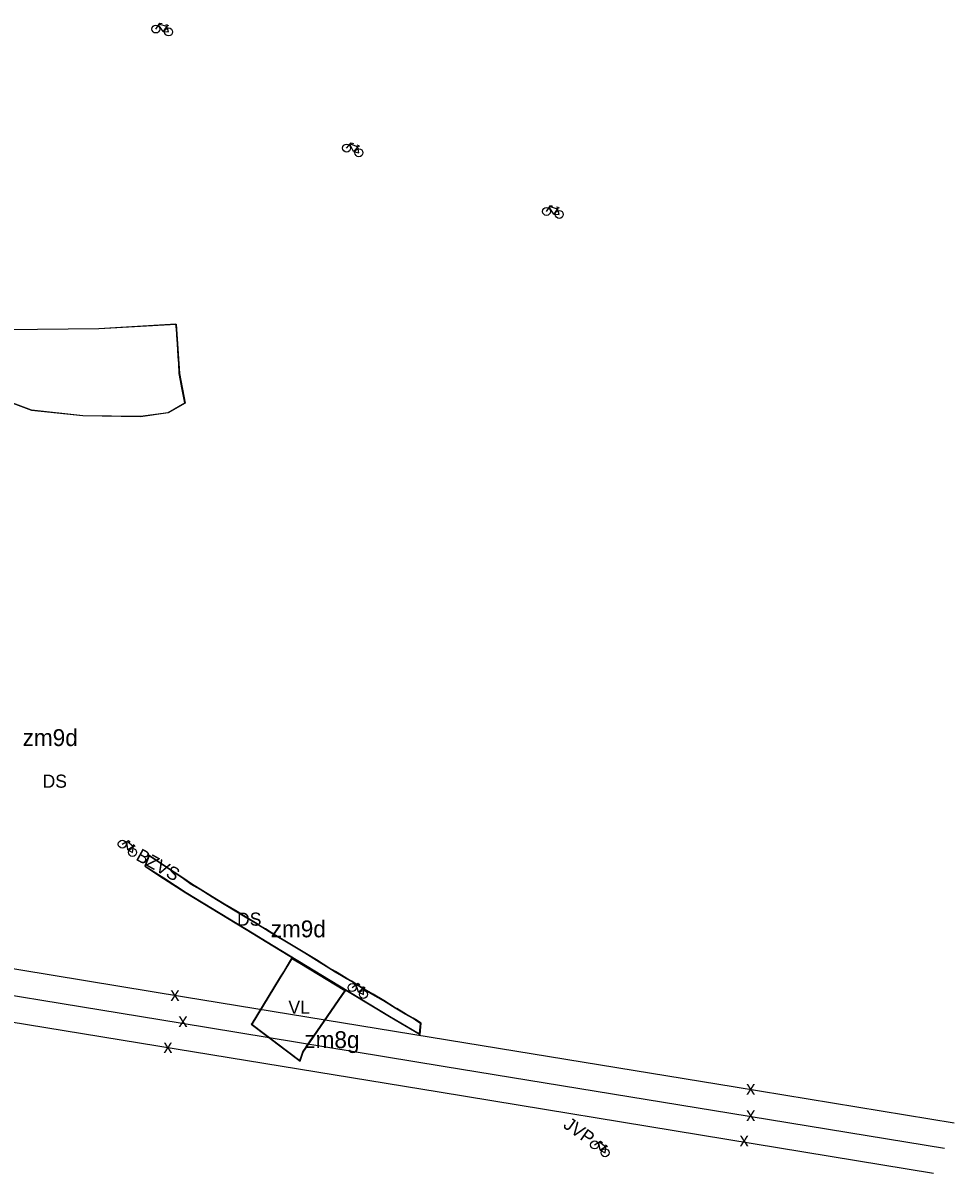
# Model space of a CAD drawing. Extents: x -555070 to -553076, y -1186731 to -1182766.
# Drawn here: x -554069 to -553076, y -1185758 to -1184531 of the extents above; entities that cross this region are included whole.
import ezdxf

# ---------------------------------------------------------------- set-up
doc = ezdxf.new("R2010")
doc.units = 0
for name, color, linetype in [('CYKLISTI_stav', 7, 'Continuous'), ('HRANICE_ZMENY_DO_KOO', 7, 'Continuous'), ('Level 10', 7, 'Continuous'), ('Level 13', 7, 'Continuous'), ('Level 29', 7, 'Continuous'), ('Level 58', 7, 'Continuous'), ('Level 59', 7, 'Continuous'), ('Level 63', 7, 'Continuous'), ('OBRYS_PLOCH', 7, 'Continuous'), ('stav_AT', 7, 'Continuous'), ('stav_DS', 7, 'Continuous'), ('stav_VL', 7, 'Continuous'), ('ZU_plocha_aktualizace', 7, 'Continuous')]:
    doc.layers.add(name, color=color, linetype=linetype)

msp = doc.modelspace()

# ---------------------------------------------------------------- linework, layer by layer
at = {"layer": 'CYKLISTI_stav'}
for p, q in [((-553963.4, -1185407.2), (-553956.8, -1185403.3)), ((-553957.5, -1185413.1), (-553958.7, -1185404.4)), ((-553958.1, -1185404), (-553951.5, -1185409.7)), ((-553950.3, -1185409), (-553957.5, -1185413.1)), ((-553956.8, -1185403.3), (-553954.9, -1185404.9)), ((-553950.3, -1185409), (-553951.7, -1185407.9)), ((-553950.3, -1185409), (-553949.6, -1185409.7)), ((-553957.5, -1185413.1), (-553952.5, -1185416)), ((-553952.5, -1185416), (-553951.5, -1185409.7)), ((-553718.1, -1185560.2), (-553712.1, -1185555.5)), ((-553713.3, -1185556.4), (-553706, -1185561.1)), ((-553712.1, -1185555.5), (-553710, -1185556.8)), ((-553711.4, -1185565.3), (-553713.8, -1185556.9)), ((-553704.9, -1185560.3), (-553711.4, -1185565.3)), ((-553711.4, -1185565.3), (-553706.1, -1185567.5)), ((-553704.9, -1185560.3), (-553706.5, -1185559.3)), ((-553706.1, -1185567.5), (-553706, -1185561.1)), ((-553704.9, -1185560.3), (-553704.1, -1185560.8)), ((-553459.3, -1185728.1), (-553452.9, -1185724)), ((-553453.2, -1185733.8), (-553454.7, -1185725.2)), ((-553454.1, -1185724.8), (-553447.4, -1185730.2)), ((-553452.9, -1185724), (-553451, -1185725.5)), ((-553446.2, -1185729.5), (-553453.2, -1185733.8)), ((-553453.2, -1185733.8), (-553448.1, -1185736.5)), ((-553448.1, -1185736.5), (-553447.4, -1185730.2)), ((-553446.2, -1185729.5), (-553447.7, -1185728.4)), ((-553446.2, -1185729.5), (-553445.5, -1185730.1))]:
    msp.add_line(p, q, dxfattribs=at)
for centre in [(-553963.4, -1185407.2), (-553952.5, -1185416), (-553718.1, -1185560.2), (-553706.1, -1185567.5), (-553459.3, -1185728.1), (-553448.1, -1185736.5)]:
    msp.add_circle(centre, 4.25, dxfattribs=at)
at = {"layer": 'HRANICE_ZMENY_DO_KOO'}
for points in [[(-554272.2, -1184853.2), (-554269.9, -1184853.2), (-554086.7, -1184858.1), (-553988.6, -1184857.1), (-553905.9, -1184852.2), (-553902.5, -1184905), (-553896.3, -1184936.5), (-553914.3, -1184946.8), (-553944.1, -1184951), (-554005.7, -1184950), (-554060.2, -1184944.2), (-554080.3, -1184936.8), (-554149.1, -1184937.6), (-554266, -1184941.4), (-554269.6, -1184937.4), (-554275.8, -1184934.4)], [(-553811, -1185510.7), (-553741.8, -1185552.6), (-553678.3, -1185591.2), (-553645.6, -1185610.4), (-553644.5, -1185598.2), (-553648.8, -1185595.5), (-553652.8, -1185593), (-553661.1, -1185588.2), (-553670.3, -1185582.7), (-553672, -1185581.7), (-553684.3, -1185574.1), (-553695.6, -1185567.4), (-553707.3, -1185560.4), (-553712.9, -1185557), (-553718.5, -1185553.5), (-553723.9, -1185550.5), (-553729.3, -1185547.1), (-553735.8, -1185543.2), (-553742.8, -1185539), (-553756, -1185530.8), (-553768.4, -1185523.2), (-553780.9, -1185515.7), (-553789.8, -1185510.3), (-553799.7, -1185504.7), (-553810.4, -1185497.7), (-553817.9, -1185493.2), (-553819.3, -1185492.3), (-553828.5, -1185486.8), (-553840.9, -1185479.2), (-553854.3, -1185471.1), (-553867.2, -1185463.3), (-553880.2, -1185455.2), (-553889.6, -1185449.6), (-553897.9, -1185443.8), (-553919.3, -1185429.6), (-553935.2, -1185418.8), (-553939.5, -1185430.8), (-553919.4, -1185443.7), (-553895.5, -1185459.2), (-553822.9, -1185503.4), (-553811, -1185510.7)]]:
    msp.add_lwpolyline(points, dxfattribs=at)
msp.add_lwpolyline([(-553795.9, -1185550.5), (-553825.2, -1185598.5), (-553825.7, -1185599.4), (-553773.6, -1185638.7), (-553771.5, -1185632.3), (-553770.4, -1185629), (-553728.8, -1185568.7), (-553725.3, -1185563.6), (-553773.7, -1185534.2), (-553782.7, -1185528.7), (-553783.2, -1185529.7), (-553785.3, -1185533.1), (-553790.4, -1185541.5), (-553790.8, -1185542.3), (-553794.8, -1185548.7)], close=True, dxfattribs=at)
at = {"layer": 'Level 13'}
for p, q in [((-553782.8, -1185529.9), (-553784.8, -1185533.4)), ((-553782.5, -1185529.4), (-553782.8, -1185529.9)), ((-553773.9, -1185534.6), (-553782.5, -1185529.4)), ((-553790.4, -1185542.5), (-553794.4, -1185549)), ((-553790, -1185541.7), (-553790.4, -1185542.5)), ((-553784.8, -1185533.4), (-553790, -1185541.7)), ((-553726, -1185563.8), (-553773.9, -1185534.6)), ((-553795.5, -1185550.8), (-553824.8, -1185598.8)), ((-553794.4, -1185549), (-553795.5, -1185550.8)), ((-553770.8, -1185628.8), (-553729.2, -1185568.4)), ((-553729.2, -1185568.4), (-553726, -1185563.8)), ((-553824.8, -1185598.8), (-553825.1, -1185599.3)), ((-553825.1, -1185599.3), (-553773.8, -1185637.9)), ((-553771.9, -1185632.1), (-553770.8, -1185628.8)), ((-553773.8, -1185637.9), (-553771.9, -1185632.1))]:
    msp.add_line(p, q, dxfattribs=at)
at = {"layer": 'Level 29'}
for points in [[(-555065.4, -1185337.6), (-554878.6, -1185437.8), (-554591.7, -1185484.8), (-554219, -1185545.9), (-553901.5, -1185597.9), (-553620.8, -1185644), (-553313.8, -1185694.3), (-553085.9, -1185731.6)], [(-553075.6, -1185704.9), (-553309.3, -1185666.6), (-553616.2, -1185616.4), (-553897, -1185570.3), (-554214.4, -1185518.3), (-554271.4, -1185509)], [(-554255.1, -1185568.4), (-554255.1, -1185568.4), (-554223.5, -1185573.6), (-553906, -1185625.6), (-553625.3, -1185671.6), (-553318.3, -1185721.9), (-553097.7, -1185758.1)]]:
    msp.add_lwpolyline(points, dxfattribs=at)
at = {"layer": 'Level 58'}
for p, q in [((-553927.6, -1184537.4), (-553923.4, -1184531)), ((-553919.7, -1184540.1), (-553924.6, -1184532.8)), ((-553924.2, -1184532.2), (-553915.9, -1184534.5)), ((-553923.4, -1184531), (-553921, -1184531.6)), ((-553915.1, -1184533.3), (-553919.7, -1184540.1)), ((-553915.1, -1184533.3), (-553916.9, -1184532.9)), ((-553914, -1184540.5), (-553915.9, -1184534.5)), ((-553915.1, -1184533.3), (-553914.1, -1184533.6)), ((-553919.7, -1184540.1), (-553914, -1184540.5)), ((-553724, -1184664.4), (-553719, -1184658.7)), ((-553716.6, -1184668.2), (-553720.4, -1184660.3)), ((-553719.9, -1184659.8), (-553712, -1184663.2)), ((-553719, -1184658.7), (-553716.7, -1184659.6)), ((-553711.1, -1184662.1), (-553716.6, -1184668.2)), ((-553716.6, -1184668.2), (-553710.9, -1184669.4)), ((-553711.1, -1184662.1), (-553712.7, -1184661.5)), ((-553710.9, -1184669.4), (-553712, -1184663.2)), ((-553711.1, -1184662.1), (-553710.1, -1184662.5)), ((-553510.6, -1184732.1), (-553506.4, -1184725.7)), ((-553502.7, -1184734.8), (-553507.6, -1184727.5)), ((-553507.2, -1184726.9), (-553498.9, -1184729.2)), ((-553506.4, -1184725.7), (-553504.1, -1184726.3)), ((-553498.1, -1184728), (-553502.7, -1184734.8)), ((-553498.1, -1184728), (-553499.9, -1184727.6)), ((-553497, -1184735.2), (-553498.9, -1184729.2)), ((-553498.1, -1184728), (-553497.2, -1184728.3)), ((-553502.7, -1184734.8), (-553497, -1184735.2))]:
    msp.add_line(p, q, dxfattribs=at)
for centre in [(-553927.6, -1184537.4), (-553914, -1184540.5), (-553724, -1184664.4), (-553710.9, -1184669.4), (-553510.6, -1184732.1), (-553497, -1184735.2)]:
    msp.add_circle(centre, 4.25, dxfattribs=at)
at = {"layer": 'OBRYS_PLOCH'}
for p, q in [((-553906.1, -1184852.4), (-553988.6, -1184857.3)), ((-553905.7, -1184857.6), (-553906.1, -1184852.4)), ((-553988.6, -1184857.3), (-554086.7, -1184858.3)), ((-554060.2, -1184944), (-554005.6, -1184949.8)), ((-554005.6, -1184949.8), (-553944.1, -1184950.8)), ((-553934.9, -1185419.6), (-553938.9, -1185430.6)), ((-553938.9, -1185430.6), (-553919.1, -1185443.3)), ((-553919.1, -1185443.3), (-553895.2, -1185458.8)), ((-553895.2, -1185458.8), (-553822.7, -1185503)), ((-553828.7, -1185487.2), (-553841.1, -1185479.7)), ((-553819.6, -1185492.7), (-553828.7, -1185487.2)), ((-553818.2, -1185493.7), (-553819.6, -1185492.7)), ((-553810.7, -1185498.2), (-553818.2, -1185493.7)), ((-553822.7, -1185503), (-553810.7, -1185510.3)), ((-553799.9, -1185505.1), (-553810.7, -1185498.2)), ((-553790, -1185510.8), (-553799.9, -1185505.1)), ((-553810.7, -1185510.3), (-553741.6, -1185552.2)), ((-553781.1, -1185516.2), (-553790, -1185510.8)), ((-553782.8, -1185529.9), (-553784.8, -1185533.4)), ((-553782.5, -1185529.4), (-553782.8, -1185529.9)), ((-553773.9, -1185534.6), (-553782.5, -1185529.4)), ((-553790.4, -1185542.5), (-553794.4, -1185549)), ((-553790, -1185541.7), (-553790.4, -1185542.5)), ((-553784.8, -1185533.4), (-553790, -1185541.7)), ((-553726, -1185563.8), (-553773.9, -1185534.6)), ((-553736.1, -1185543.7), (-553743.1, -1185539.4)), ((-553729.5, -1185547.6), (-553736.1, -1185543.7)), ((-553795.5, -1185550.8), (-553824.8, -1185598.8)), ((-553794.4, -1185549), (-553795.5, -1185550.8)), ((-553741.6, -1185552.2), (-553678.1, -1185590.8)), ((-553724.2, -1185550.9), (-553729.5, -1185547.6)), ((-553718.8, -1185553.9), (-553724.2, -1185550.9)), ((-553713.2, -1185557.4), (-553718.8, -1185553.9)), ((-553770.8, -1185628.8), (-553729.2, -1185568.4)), ((-553729.2, -1185568.4), (-553726, -1185563.8)), ((-553707.6, -1185560.8), (-553713.2, -1185557.4)), ((-553695.9, -1185567.8), (-553707.6, -1185560.8)), ((-553684.6, -1185574.5), (-553695.9, -1185567.8)), ((-553672.3, -1185582.1), (-553684.6, -1185574.5)), ((-553678.1, -1185590.8), (-553646, -1185609.6)), ((-553670.5, -1185583.1), (-553672.3, -1185582.1)), ((-553661.3, -1185588.7), (-553670.5, -1185583.1)), ((-553653.1, -1185593.4), (-553661.3, -1185588.7)), ((-553824.8, -1185598.8), (-553825.1, -1185599.3)), ((-553825.1, -1185599.3), (-553773.8, -1185637.9)), ((-553646, -1185609.6), (-553645.1, -1185598.5)), ((-553771.9, -1185632.1), (-553770.8, -1185628.8)), ((-553773.8, -1185637.9), (-553771.9, -1185632.1))]:
    msp.add_line(p, q, dxfattribs=at)
for points in [[(-553944.1, -1184950.8), (-553914.4, -1184946.6), (-553896.5, -1184936.4), (-553897.2, -1184932.7), (-553899, -1184923.7), (-553899.7, -1184920.2), (-553900.4, -1184916.5), (-553901.6, -1184910.8), (-553902.7, -1184905), (-553903, -1184894.4), (-553903.4, -1184890.7), (-553903.7, -1184887), (-553904.2, -1184879.7), (-553904.5, -1184874), (-553904.8, -1184868.4), (-553905.2, -1184864.5), (-553905.3, -1184863.5), (-553905.7, -1184857.6)], [(-554149.1, -1184937.4), (-554090.8, -1184936.2), (-554087.1, -1184935.9), (-554080.2, -1184936.6), (-554060.2, -1184944)], [(-553898.2, -1185444.2), (-553919.6, -1185430), (-553934.9, -1185419.6)], [(-553880.4, -1185455.6), (-553889.9, -1185450.1), (-553898.2, -1185444.2)], [(-553841.1, -1185479.7), (-553854.5, -1185471.6), (-553867.5, -1185463.7), (-553880.4, -1185455.6)], [(-553743.1, -1185539.4), (-553756.2, -1185531.3), (-553768.7, -1185523.6), (-553781.1, -1185516.2)], [(-553645.1, -1185598.5), (-553649.1, -1185595.9), (-553653.1, -1185593.4)]]:
    msp.add_lwpolyline(points, dxfattribs=at)
at = {"layer": 'stav_AT'}
for p, q in [((-553906.1, -1184852.4), (-553988.6, -1184857.3)), ((-553905.7, -1184857.6), (-553906.1, -1184852.4)), ((-553988.6, -1184857.3), (-554086.7, -1184858.3)), ((-554060.2, -1184944), (-554005.6, -1184949.8)), ((-554005.6, -1184949.8), (-553944.1, -1184950.8))]:
    msp.add_line(p, q, dxfattribs=at)
for points in [[(-553944.1, -1184950.8), (-553914.4, -1184946.6), (-553896.5, -1184936.4), (-553897.2, -1184932.7), (-553899, -1184923.7), (-553899.7, -1184920.2), (-553900.4, -1184916.5), (-553901.6, -1184910.8), (-553902.7, -1184905), (-553903, -1184894.4), (-553903.4, -1184890.7), (-553903.7, -1184887), (-553904.2, -1184879.7), (-553904.5, -1184874), (-553904.8, -1184868.4), (-553905.2, -1184864.5), (-553905.3, -1184863.5), (-553905.7, -1184857.6)], [(-554149.1, -1184937.4), (-554090.8, -1184936.2), (-554087.1, -1184935.9), (-554080.2, -1184936.6), (-554060.2, -1184944)]]:
    msp.add_lwpolyline(points, dxfattribs=at)
at = {"layer": 'stav_DS'}
for p, q in [((-553934.9, -1185419.6), (-553938.9, -1185430.6)), ((-553938.9, -1185430.6), (-553919.1, -1185443.3)), ((-553919.1, -1185443.3), (-553895.2, -1185458.8)), ((-553895.2, -1185458.8), (-553822.7, -1185503)), ((-553828.7, -1185487.2), (-553841.1, -1185479.7)), ((-553819.6, -1185492.7), (-553828.7, -1185487.2)), ((-553818.2, -1185493.7), (-553819.6, -1185492.7)), ((-553810.7, -1185498.2), (-553818.2, -1185493.7)), ((-553822.7, -1185503), (-553810.7, -1185510.3)), ((-553799.9, -1185505.1), (-553810.7, -1185498.2)), ((-553790, -1185510.8), (-553799.9, -1185505.1)), ((-553810.7, -1185510.3), (-553741.6, -1185552.2)), ((-553781.1, -1185516.2), (-553790, -1185510.8)), ((-553736.1, -1185543.7), (-553743.1, -1185539.4)), ((-553729.5, -1185547.6), (-553736.1, -1185543.7)), ((-553741.6, -1185552.2), (-553678.1, -1185590.8)), ((-553724.2, -1185550.9), (-553729.5, -1185547.6)), ((-553718.8, -1185553.9), (-553724.2, -1185550.9)), ((-553713.2, -1185557.4), (-553718.8, -1185553.9)), ((-553707.6, -1185560.8), (-553713.2, -1185557.4)), ((-553695.9, -1185567.8), (-553707.6, -1185560.8)), ((-553684.6, -1185574.5), (-553695.9, -1185567.8)), ((-553672.3, -1185582.1), (-553684.6, -1185574.5)), ((-553678.1, -1185590.8), (-553646, -1185609.6)), ((-553670.5, -1185583.1), (-553672.3, -1185582.1)), ((-553661.3, -1185588.7), (-553670.5, -1185583.1)), ((-553653.1, -1185593.4), (-553661.3, -1185588.7)), ((-553646, -1185609.6), (-553645.1, -1185598.5))]:
    msp.add_line(p, q, dxfattribs=at)
for points in [[(-553898.2, -1185444.2), (-553919.6, -1185430), (-553934.9, -1185419.6)], [(-553880.4, -1185455.6), (-553889.9, -1185450.1), (-553898.2, -1185444.2)], [(-553841.1, -1185479.7), (-553854.5, -1185471.6), (-553867.5, -1185463.7), (-553880.4, -1185455.6)], [(-553743.1, -1185539.4), (-553756.2, -1185531.3), (-553768.7, -1185523.6), (-553781.1, -1185516.2)], [(-553645.1, -1185598.5), (-553649.1, -1185595.9), (-553653.1, -1185593.4)]]:
    msp.add_lwpolyline(points, dxfattribs=at)
at = {"layer": 'stav_VL'}
for p, q in [((-553782.8, -1185529.9), (-553784.8, -1185533.4)), ((-553782.5, -1185529.4), (-553782.8, -1185529.9)), ((-553773.9, -1185534.6), (-553782.5, -1185529.4)), ((-553790.4, -1185542.5), (-553794.4, -1185549)), ((-553790, -1185541.7), (-553790.4, -1185542.5)), ((-553784.8, -1185533.4), (-553790, -1185541.7)), ((-553726, -1185563.8), (-553773.9, -1185534.6)), ((-553795.5, -1185550.8), (-553824.8, -1185598.8)), ((-553794.4, -1185549), (-553795.5, -1185550.8)), ((-553770.8, -1185628.8), (-553729.2, -1185568.4)), ((-553729.2, -1185568.4), (-553726, -1185563.8)), ((-553824.8, -1185598.8), (-553825.1, -1185599.3)), ((-553825.1, -1185599.3), (-553773.8, -1185637.9)), ((-553771.9, -1185632.1), (-553770.8, -1185628.8)), ((-553773.8, -1185637.9), (-553771.9, -1185632.1))]:
    msp.add_line(p, q, dxfattribs=at)
at = {"layer": 'ZU_plocha_aktualizace'}
for p, q in [((-553782.8, -1185529.9), (-553784.8, -1185533.4)), ((-553782.5, -1185529.4), (-553782.8, -1185529.9)), ((-553773.9, -1185534.6), (-553782.5, -1185529.4)), ((-553790.4, -1185542.5), (-553794.4, -1185549)), ((-553790, -1185541.7), (-553790.4, -1185542.5)), ((-553784.8, -1185533.4), (-553790, -1185541.7)), ((-553726, -1185563.8), (-553773.9, -1185534.6)), ((-553795.5, -1185550.8), (-553824.8, -1185598.8)), ((-553794.4, -1185549), (-553795.5, -1185550.8)), ((-553770.8, -1185628.8), (-553729.2, -1185568.4)), ((-553729.2, -1185568.4), (-553726, -1185563.8)), ((-553824.8, -1185598.8), (-553825.1, -1185599.3)), ((-553825.1, -1185599.3), (-553773.8, -1185637.9)), ((-553771.9, -1185632.1), (-553770.8, -1185628.8)), ((-553773.8, -1185637.9), (-553771.9, -1185632.1))]:
    msp.add_line(p, q, dxfattribs=at)

# ---------------------------------------------------------------- texts
at = {"layer": 'CYKLISTI_stav'}
for s, rotation, p in [('BZVS', 330.8645, (-553949.9, -1185423.5)), ('JVP', 324.5635, (-553493.8, -1185708.9))]:
    msp.add_text(s, height=14, rotation=rotation, dxfattribs=at).set_placement(p)
at = {"layer": 'Level 10'}
for s, p in [('zm9d', (-554069.8, -1185302.5)), ('zm9d', (-553805, -1185506.6)), ('zm8g', (-553769.1, -1185624.8))]:
    msp.add_text(s, height=18, dxfattribs=at).set_placement(p)
at = {"layer": 'Level 29'}
for p in [(-553912.1, -1185574.5), (-553903.5, -1185602.3), (-553919.6, -1185630.1), (-553297.5, -1185674.5), (-553297.5, -1185702.6), (-553304.5, -1185729.6)]:
    msp.add_text('x', height=14.6, rotation=0.008, dxfattribs=at).set_placement(p)
at = {"layer": 'Level 59'}
for p in [(-554048.5, -1185347), (-553840.9, -1185494.2)]:
    msp.add_text('DS', height=14, dxfattribs=at).set_placement(p)
at = {"layer": 'Level 63'}
msp.add_text('VL', height=14, dxfattribs=at).set_placement((-553786.1, -1185588.2))

doc.saveas('drawing.dxf')
